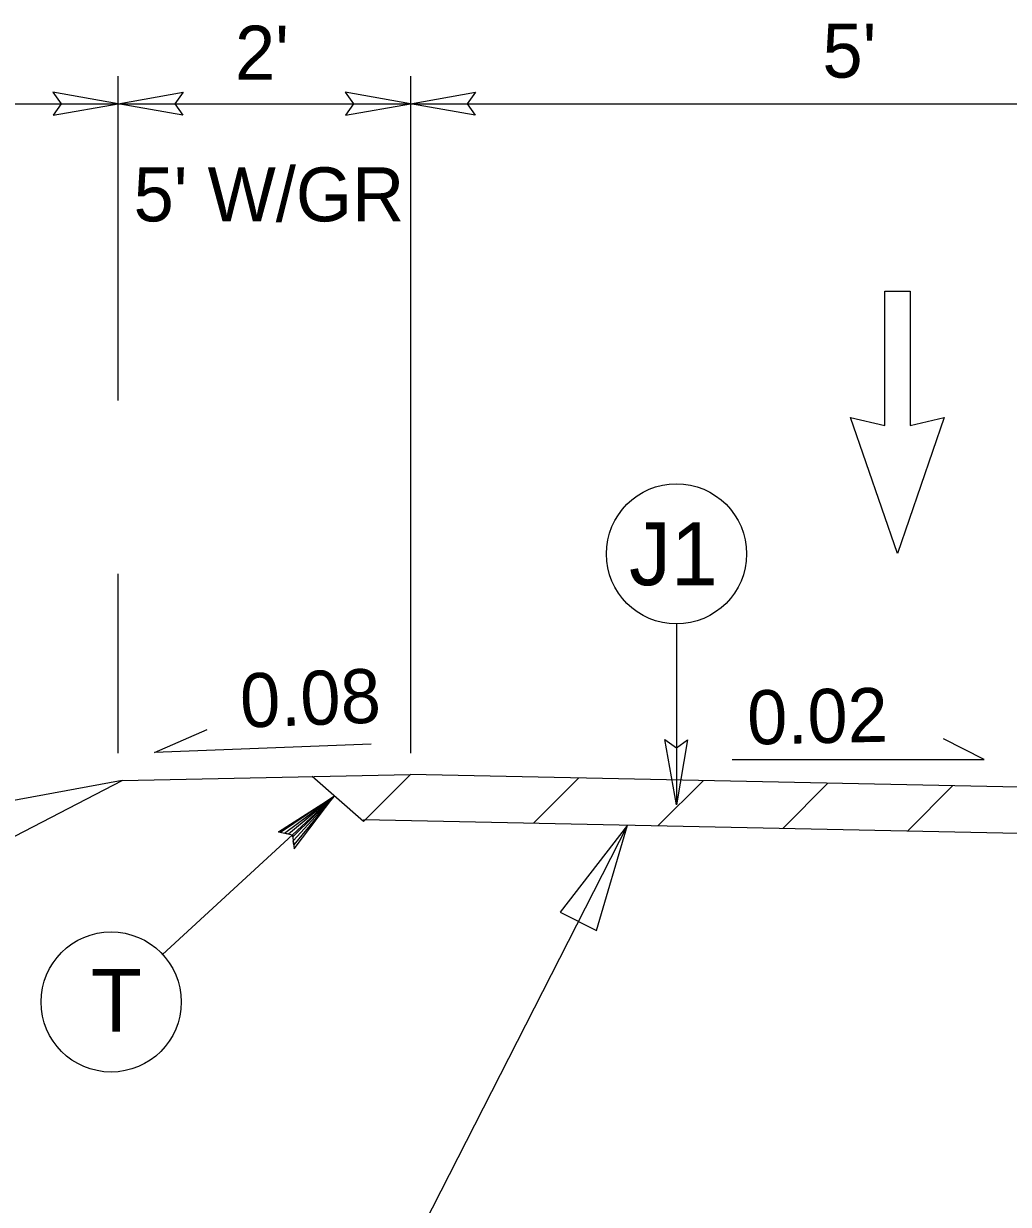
# Model space of a CAD drawing. Extents: x 1542177 to 1542464, y 45134 to 45344.
# Drawn here: x 1542288.32 to 1542299.26, y 45194.34 to 45207.45 of the extents above; entities that cross this region are included whole.
import ezdxf

# ---------------------------------------------------------------- set-up
doc = ezdxf.new("R2010")
doc.units = 0
for name, color, linetype in [('Default', 7, 'Continuous'), ('Old_Level_2', 7, 'Continuous'), ('Typical Detail Wedge3 CELL', 7, 'Continuous'), ('Typical ID Circle CELL', 7, 'Continuous'), ('Typical Text ID Circle CELL', 7, 'Continuous')]:
    doc.layers.add(name, color=color, linetype=linetype)

# ---------------------------------------------------------------- blocks, each defined once
blk = doc.blocks.new('ARROW3_1')
at = {"layer": 'Default'}
blk.add_lwpolyline([(-0.0267, -0.5547), (-0.0267, -0.2704), (-0.0991, -0.2874), (0, 0), (0.099, -0.2874), (0.0267, -0.2704), (0.0267, -0.5547), (-0.0267, -0.5547)], dxfattribs=at)
blk = doc.blocks.new('CIR')
at = {"layer": 'Default'}
blk.add_line((0, 1.914), (0, 0), dxfattribs=at)
blk.add_lwpolyline([(0.118, 0.686), (0, 0), (-0.122, 0.69), (0, 0.602)], close=True, dxfattribs=at)
blk.add_circle((0, 2.654), 0.741, dxfattribs=at)

msp = doc.modelspace()

# ---------------------------------------------------------------- linework, layer by layer
at = {"layer": 'Default'}
for p, q in [((1542289.373, 45203.267), (1542289.373, 45206.867)), ((1542292.625, 45199.353), (1542292.625, 45206.867)), ((1542283.461, 45206.56), (1542289.373, 45206.56)), ((1542289.373, 45206.56), (1542292.62, 45206.56)), ((1542292.62, 45206.56), (1542302.22, 45206.56)), ((1542292.62, 45206.56), (1542302.22, 45206.56)), ((1542289.373, 45199.353), (1542289.373, 45201.344)), ((1542289.777, 45199.359), (1542290.365, 45199.614)), ((1542298.993, 45199.283), (1542298.54, 45199.511)), ((1542298.993, 45199.283), (1542298.54, 45199.511)), ((1542292.183, 45199.45), (1542289.777, 45199.359)), ((1542296.193, 45199.283), (1542298.993, 45199.283)), ((1542296.193, 45199.283), (1542298.993, 45199.283)), ((1542289.419, 45199.047), (1542292.619, 45199.114)), ((1542292.101, 45198.594), (1542291.529, 45199.091)), ((1542292.101, 45198.594), (1542292.619, 45199.113)), ((1542302.22, 45198.914), (1542292.619, 45199.114)), ((1542293.987, 45198.576), (1542294.486, 45199.075)), ((1542278.251, 45193.26), (1542289.419, 45199.047)), ((1542289.419, 45199.047), (1542283.461, 45197.957)), ((1542295.373, 45198.547), (1542295.872, 45199.046)), ((1542296.758, 45198.518), (1542297.257, 45199.017)), ((1542298.143, 45198.489), (1542298.642, 45198.988)), ((1542292.099, 45198.615), (1542302.22, 45198.404))]:
    msp.add_line(p, q, dxfattribs=at)
for points in [[(1542288.653, 45206.436), (1542289.373, 45206.56), (1542288.649, 45206.688), (1542288.741, 45206.56)], [(1542288.653, 45206.436), (1542289.373, 45206.56), (1542288.649, 45206.688), (1542288.741, 45206.56)], [(1542290.093, 45206.436), (1542289.373, 45206.56), (1542290.097, 45206.688), (1542290.005, 45206.56)], [(1542291.9, 45206.436), (1542292.62, 45206.56), (1542291.896, 45206.688), (1542291.988, 45206.56)], [(1542291.9, 45206.436), (1542292.62, 45206.56), (1542291.896, 45206.688), (1542291.988, 45206.56)], [(1542293.34, 45206.436), (1542292.62, 45206.56), (1542293.344, 45206.688), (1542293.252, 45206.56)], [(1542293.34, 45206.436), (1542292.62, 45206.56), (1542293.344, 45206.688), (1542293.252, 45206.56)]]:
    msp.add_lwpolyline(points, close=True, dxfattribs=at)
at = {"layer": 'Old_Level_2'}
msp.add_lwpolyline([(1542295.03, 45198.554), (1542289.657, 45188.016), (1542288.595, 45188.015)], dxfattribs=at)
msp.add_lwpolyline([(1542294.686, 45197.383), (1542295.03, 45198.554), (1542294.285, 45197.587)], close=True, dxfattribs=at)
at = {"layer": 'Typical Detail Wedge3 CELL'}
msp.add_lwpolyline([(1542291.155, 45198.477), (1542291.31, 45198.447), (1542291.329, 45198.289), (1542291.77, 45198.871), (1542291.324, 45198.334), (1542291.319, 45198.38), (1542291.77, 45198.871), (1542291.314, 45198.423), (1542291.31, 45198.447), (1542291.77, 45198.871), (1542291.267, 45198.454), (1542291.223, 45198.463), (1542291.77, 45198.871), (1542291.178, 45198.472), (1542291.155, 45198.477), (1542291.77, 45198.871)], dxfattribs=at)
at = {"layer": 'Typical ID Circle CELL'}
msp.add_line((1542289.868, 45197.117), (1542291.31, 45198.447), dxfattribs=at)
msp.add_circle((1542289.297, 45196.59), 0.778, dxfattribs=at)

# ---------------------------------------------------------------- block references
at = {"layer": 'Default', "xscale": 5.249333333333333, "yscale": 5.249333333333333, "rotation": 180}
msp.add_blockref('ARROW3_1', (1542298.029, 45201.569), dxfattribs=at)
at = {"layer": 'Default', "xscale": 1.0498642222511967, "yscale": 1.0498642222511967}
msp.add_blockref('CIR', (1542295.575, 45198.778), dxfattribs=at)

# ---------------------------------------------------------------- texts
at = {"layer": 'Default'}
for s, height, p in [("2'", 0.6, (1542290.672, 45206.828)), ("5'", 0.6, (1542297.196, 45206.851)), ("5' W/GR", 0.6, (1542289.546, 45205.255)), ('J1', 0.6982, (1542295.048, 45201.216))]:
    msp.add_text(s, height=height, dxfattribs=at).set_placement(p)
for s, rotation, p in [('0.08', 2.1798, (1542290.74, 45199.634)), ('0.02', 1.1916, (1542296.366, 45199.447))]:
    msp.add_text(s, height=0.6, rotation=rotation, dxfattribs=at).set_placement(p)
at = {"layer": 'Typical Text ID Circle CELL'}
msp.add_text('T', height=0.696, dxfattribs=at).set_placement((1542289.069, 45196.261))

doc.saveas('drawing.dxf')
